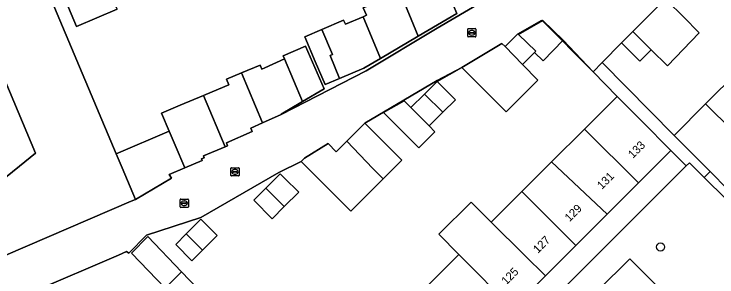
# Model space of a CAD drawing. Extents: x 159960 to 160866, y 382700 to 383354.
# Drawn here: x 160180.5 to 160265.7, y 383247.3 to 383279.2 of the extents above; entities that cross this region are included whole.
import ezdxf

# ---------------------------------------------------------------- set-up
doc = ezdxf.new("R2010")
doc.units = 0
for name, color, linetype in [('IMGEO_Boom', 7, 'Continuous'), ('IMGEO_Erf', 7, 'Continuous'), ('IMGEO_Hek', 7, 'Continuous'), ('IMGEO_Kolk', 7, 'Continuous'), ('IMGEO_Muur', 7, 'Continuous'), ('IMGEO_Pand', 7, 'Continuous'), ('IMGEO_Pand_nummerreeks', 7, 'Continuous'), ('IMGEO_Parkeervlak_open', 7, 'Continuous'), ('IMGEO_Rijbaan_lokaal_open', 7, 'Continuous'), ('IMGEO_Rioolput', 7, 'Continuous'), ('IMGEO_Voetpad_open', 7, 'Continuous')]:
    doc.layers.add(name, color=color, linetype=linetype)

msp = doc.modelspace()

# ---------------------------------------------------------------- linework, layer by layer
at = {"layer": 'IMGEO_Boom'}
msp.add_circle((160258.856, 383250.978), 0.489, dxfattribs=at)
at = {"layer": 'IMGEO_Erf'}
for points in [[(160266.216, 383293.194), (160261.754, 383290.535), (160263.274, 383287.861), (160261.51, 383286.857), (160261.743, 383286.447), (160262.389, 383285.314), (160264.398, 383283.518), (160259.67, 383280.828), (160261.621, 383278.874), (160263.551, 383276.941), (160259.686, 383272.913), (160257.707, 383274.874), (160256.335, 383273.504), (160254.138, 383275.705), (160251.785, 383273.342), (160260.491, 383264.497), (160264.32, 383268.32), (160268.247, 383272.242)], [(160183.004, 383285.712), (160192.859, 383262.277), (160199.282, 383265.002), (160198.369, 383267.186), (160200.633, 383268.147), (160203.442, 383269.339), (160203.718, 383269.456), (160206.503, 383270.638), (160206.224, 383271.296), (160208.052, 383272.072), (160210.311, 383273.03), (160210.519, 383272.54), (160210.88, 383272.7), (160213.279, 383273.761), (160213.118, 383274.125), (160215.792, 383275.307), (160218.073, 383270.149), (160215.452, 383268.606), (160213.76, 383267.611), (160213.267, 383267.321), (160212.842, 383267.071), (160212.865, 383267.016), (160223.145, 383272.34), (160231.792, 383277.479), (160248.64, 383287.39)], [(160192.97, 383279.801), (160188.056, 383277.715), (160186.423, 383281.562)], [(160230.525, 383246.193), (160234.338, 383250), (160234.412, 383250.073), (160231.985, 383252.518), (160235.896, 383256.424), (160238.338, 383253.994), (160242.052, 383257.703), (160245.647, 383261.293), (160249.618, 383265.258), (160253.591, 383269.225), (160250.674, 383272.217), (160247.039, 383276.034), (160244.609, 383273.533), (160243.565, 383274.546), (160242.115, 383273.097), (160243.971, 383271.194), (160240.133, 383267.363), (160234.771, 383272.735), (160231.773, 383271.153), (160223.016, 383266.001), (160227.495, 383261.515), (160225.213, 383259.237), (160221.301, 383255.332), (160220.102, 383256.532), (160215.296, 383261.343), (160212.589, 383260.015), (160203.125, 383254.533), (160196.55, 383252.407), (160194.374, 383250.234), (160194.125, 383250.434), (160193.118, 383250), (160182.733, 383245.525)], [(160208.233, 383207.203), (160251.131, 383250), (160261.979, 383260.823), (160260.119, 383262.687), (160256.164, 383258.737), (160252.364, 383254.944), (160248.59, 383251.176), (160247.413, 383250), (160244.887, 383247.478), (160240.918, 383243.515)], [(160267.032, 383257.946), (160264.852, 383260.129), (160264.14, 383259.417), (160269.505, 383254.094)]]:
    msp.add_lwpolyline(points, dxfattribs=at)
for points in [[(160231.939, 383284.582), (160234.143, 383279.263), (160229.485, 383276.528), (160224.882, 383273.826), (160222.897, 383272.661), (160219.927, 383271.4), (160218.177, 383270.657), (160216.997, 383273.438), (160215.712, 383276.465), (160217.781, 383277.343), (160220.432, 383278.468), (160220.641, 383277.976), (160222.782, 383278.884), (160223.197, 383279.06), (160222.807, 383279.979), (160227.268, 383281.872), (160227.355, 383281.909), (160227.093, 383282.525)], [(160229.56, 383263.005), (160225.282, 383267.288), (160227.765, 383268.699), (160228.302, 383268.161), (160228.599, 383267.864), (160230.237, 383269.5), (160231.791, 383271.051), (160233.98, 383268.829), (160232.444, 383267.296), (160230.803, 383265.657), (160231.508, 383264.951)], [(160211.774, 383254.407), (160209.542, 383256.642), (160211.003, 383258.1), (160212.757, 383259.851), (160213.279, 383259.328), (160214.989, 383257.616), (160213.236, 383255.866)], [(160202.046, 383249.296), (160200.068, 383251.276), (160201.356, 383252.562), (160203.129, 383254.333), (160205.107, 383252.351), (160203.328, 383250.576)], [(160200.785, 383247.974), (160204.653, 383243.924), (160202.66, 383241.936), (160198.783, 383245.978), (160194.708, 383250.244), (160196.709, 383252.241)]]:
    msp.add_lwpolyline(points, close=True, dxfattribs=at)
at = {"layer": 'IMGEO_Hek'}
msp.add_lwpolyline([(160251.785, 383273.342), (160254.138, 383275.705)], dxfattribs=at)
at = {"layer": 'IMGEO_Kolk'}
for p, q in [((160235.471, 383276.517), (160235.471, 383277.369)), ((160235.546, 383277.443), (160236.398, 383277.443)), ((160235.73, 383276.937), (160235.73, 383276.949)), ((160236.168, 383276.9), (160235.77, 383276.9)), ((160235.773, 383276.986), (160236.171, 383276.986)), ((160235.959, 383277.223), (160235.984, 383277.223)), ((160236.214, 383276.949), (160236.214, 383276.937)), ((160236.472, 383277.369), (160236.472, 383276.517)), ((160236.398, 383276.443), (160235.546, 383276.443)), ((160235.982, 383276.663), (160235.957, 383276.663)), ((160206.837, 383260.585), (160207.689, 383260.585)), ((160206.762, 383259.659), (160206.762, 383260.511)), ((160207.021, 383260.079), (160207.021, 383260.091)), ((160207.459, 383260.042), (160207.061, 383260.042)), ((160207.064, 383260.128), (160207.462, 383260.128)), ((160207.273, 383259.805), (160207.248, 383259.805)), ((160207.25, 383260.365), (160207.275, 383260.365)), ((160207.505, 383260.091), (160207.505, 383260.079)), ((160207.763, 383260.511), (160207.763, 383259.659)), ((160207.689, 383259.585), (160206.837, 383259.585))]:
    msp.add_line(p, q, dxfattribs=at)
for points in [[(160235.471, 383276.517), (160235.471, 383277.369)], [(160235.546, 383277.443), (160236.398, 383277.443)], [(160236.472, 383277.369), (160236.472, 383276.517)], [(160236.398, 383276.443), (160235.546, 383276.443)], [(160206.837, 383260.585), (160207.689, 383260.585)], [(160206.762, 383259.659), (160206.762, 383260.511)], [(160207.763, 383260.511), (160207.763, 383259.659)], [(160207.689, 383259.585), (160206.837, 383259.585)]]:
    msp.add_lwpolyline(points, dxfattribs=at)
for centre, radius, start, end in [((160235.548, 383277.367), 0.0765, 91.55205, 178.44795), ((160235.548, 383277.367), 0.0765, 91.55205, 178.44795), ((160235.77, 383276.946), 0.0403, 85.87752, 175.75265), ((160235.767, 383276.936), 0.0366, 178.93798, 274.71019), ((160236.171, 383276.943), 0.043, 264.86636, 352.45326), ((160236.175, 383276.948), 0.0386, 1.73085, 96.63898), ((160236.396, 383277.367), 0.0765, 1.55205, 88.44795), ((160236.396, 383277.367), 0.0765, 1.55205, 88.44795), ((160235.548, 383276.519), 0.0765, 181.55205, 268.44795), ((160235.548, 383276.519), 0.0765, 181.55205, 268.44795), ((160236.396, 383276.519), 0.0765, 271.55205, 358.44795), ((160236.396, 383276.519), 0.0765, 271.55205, 358.44795), ((160206.839, 383260.509), 0.0765, 91.55205, 178.44795), ((160206.839, 383260.509), 0.0765, 91.55205, 178.44795), ((160207.687, 383260.509), 0.0765, 1.55205, 88.44795), ((160207.687, 383260.509), 0.0765, 1.55205, 88.44795), ((160207.061, 383260.088), 0.0403, 85.87752, 175.75265), ((160207.058, 383260.078), 0.0366, 178.93798, 274.71019), ((160207.462, 383260.085), 0.043, 264.86636, 352.45326), ((160207.466, 383260.09), 0.0386, 1.73085, 96.63898), ((160206.839, 383259.661), 0.0765, 181.55205, 268.44795), ((160206.839, 383259.661), 0.0765, 181.55205, 268.44795), ((160207.687, 383259.661), 0.0765, 271.55205, 358.44795), ((160207.687, 383259.661), 0.0765, 271.55205, 358.44795)]:
    msp.add_arc(centre, radius, start, end, dxfattribs=at)
for centre, major_axis, ratio, start_param, end_param in [((160235.958, 383276.943), (-0.387, 0.002), 0.722429, 4.712389, 7.853982), ((160235.983, 383276.943), (-0.39, 0.002), 0.717154, 1.570796, 4.712389), ((160207.249, 383260.085), (-0.387, 0.002), 0.722429, 4.712389, 7.853982), ((160207.274, 383260.085), (-0.39, 0.002), 0.717154, 1.570796, 4.712389)]:
    msp.add_ellipse(centre, major_axis=major_axis, ratio=ratio, start_param=start_param, end_param=end_param, dxfattribs=at)
at = {"layer": 'IMGEO_Muur'}
for points in [[(160241.543, 383276.818), (160244.454, 383278.474), (160250.674, 383272.217)], [(160231.791, 383271.051), (160234.771, 383272.735)]]:
    msp.add_lwpolyline(points, dxfattribs=at)
at = {"layer": 'IMGEO_Pand'}
for points in [[(160183.004, 383285.712), (160181.841, 383288.432), (160181.644, 383288.894), (160181.208, 383288.685), (160173.362, 383285.397), (160183.09, 383262.358), (160173.574, 383254.679), (160178.179, 383250), (160178.563, 383249.609), (160179.477, 383250), (160194.681, 383256.511), (160195.189, 383256.729), (160193.573, 383260.577), (160192.859, 383262.277)], [(160189.337, 383288.318), (160185.578, 383286.722), (160184.438, 383286.238), (160186.423, 383281.562), (160188.056, 383277.715), (160192.97, 383279.801)], [(160183.09, 383262.358), (160173.362, 383285.397), (160163.306, 383284.974), (160163.378, 383283.205), (160163.482, 383280.605), (160164.075, 383268.216), (160167.723, 383268.339), (160167.679, 383269.669), (160168.759, 383269.706), (160168.726, 383270.685), (160172.805, 383270.823), (160175.164, 383270.903), (160178.228, 383263.099), (160164.266, 383262.534), (160164.765, 383250), (160164.849, 383247.905), (160167.549, 383250), (160173.574, 383254.679)], [(160234.143, 383279.263), (160231.939, 383284.582), (160227.093, 383282.525), (160227.355, 383281.909), (160227.268, 383281.872), (160229.485, 383276.528)], [(160224.882, 383273.826), (160229.485, 383276.528), (160227.268, 383281.872), (160222.807, 383279.979), (160223.197, 383279.06), (160222.782, 383278.884)], [(160259.67, 383280.828), (160259.498, 383281.119), (160255.486, 383277.074), (160257.707, 383274.874), (160259.686, 383272.913), (160263.551, 383276.941), (160261.621, 383278.874)], [(160224.882, 383273.826), (160222.782, 383278.884), (160220.641, 383277.976), (160220.432, 383278.468), (160217.781, 383277.343), (160219.066, 383274.317), (160218.785, 383274.198), (160219.927, 383271.4), (160222.897, 383272.661)], [(160241.652, 383276.713), (160243.737, 383274.715), (160243.565, 383274.546), (160244.609, 383273.533), (160247.039, 383276.034), (160244.585, 383278.418)], [(160218.785, 383274.198), (160219.066, 383274.317), (160217.781, 383277.343), (160215.712, 383276.465), (160216.997, 383273.438), (160218.177, 383270.657), (160219.927, 383271.4)], [(160241.652, 383276.713), (160241.543, 383276.818), (160239.998, 383275.267), (160242.115, 383273.097), (160243.565, 383274.546), (160243.737, 383274.715)], [(160255.486, 383277.074), (160254.138, 383275.705), (160256.335, 383273.504), (160257.707, 383274.874)], [(160215.452, 383268.606), (160218.073, 383270.149), (160215.792, 383275.307), (160213.118, 383274.125), (160213.279, 383273.761)], [(160242.115, 383273.097), (160239.998, 383275.267), (160239.609, 383275.636), (160234.771, 383272.735), (160240.133, 383267.363), (160243.971, 383271.194)], [(160213.279, 383273.761), (160210.88, 383272.7), (160210.519, 383272.54), (160210.311, 383273.03), (160208.052, 383272.072), (160210.605, 383266.014), (160212.865, 383267.016), (160212.842, 383267.071), (160213.267, 383267.321), (160213.76, 383267.611), (160215.452, 383268.606)], [(160208.052, 383272.072), (160206.224, 383271.296), (160206.503, 383270.638), (160203.718, 383269.456), (160203.442, 383269.339), (160206.057, 383263.124), (160206.37, 383263.255), (160206.241, 383263.589), (160209.326, 383264.979), (160209.161, 383265.373), (160210.605, 383266.014)], [(160274.821, 383265.724), (160268.247, 383272.242), (160264.32, 383268.32), (160270.895, 383261.804)], [(160232.444, 383267.296), (160233.98, 383268.829), (160231.791, 383271.051), (160230.237, 383269.5)], [(160199.282, 383265.002), (160200.005, 383263.307), (160201.168, 383260.566), (160203.299, 383261.469), (160203.216, 383261.652), (160203.536, 383261.793), (160203.429, 383262.024), (160206.057, 383263.124), (160203.442, 383269.339), (160200.633, 383268.147), (160198.369, 383267.186)], [(160232.444, 383267.296), (160230.237, 383269.5), (160228.599, 383267.864), (160230.803, 383265.657)], [(160249.618, 383265.258), (160256.164, 383258.737), (160260.119, 383262.687), (160256.586, 383266.225), (160253.591, 383269.225)], [(160228.599, 383267.864), (160228.302, 383268.161), (160227.765, 383268.699), (160225.282, 383267.288), (160229.56, 383263.005), (160231.508, 383264.951), (160230.803, 383265.657)], [(160264.32, 383268.32), (160260.491, 383264.497), (160264.852, 383260.129), (160267.032, 383257.946), (160270.895, 383261.804)], [(160220.807, 383263.786), (160223.977, 383260.476), (160225.213, 383259.237), (160227.495, 383261.515), (160223.016, 383266.001)], [(160199.282, 383265.002), (160192.859, 383262.277), (160193.573, 383260.577), (160195.189, 383256.729), (160199.573, 383259.303), (160199.273, 383259.763), (160201.168, 383260.566), (160200.005, 383263.307)], [(160249.618, 383265.258), (160245.647, 383261.293), (160252.364, 383254.944), (160256.164, 383258.737)], [(160220.807, 383263.786), (160219.525, 383262.501), (160218.554, 383263.505), (160215.697, 383261.743), (160215.296, 383261.343), (160220.102, 383256.532), (160221.301, 383255.332), (160225.213, 383259.237), (160223.977, 383260.476)], [(160242.052, 383257.703), (160248.59, 383251.176), (160252.364, 383254.944), (160245.647, 383261.293)], [(160213.236, 383255.866), (160214.989, 383257.616), (160213.279, 383259.328), (160212.757, 383259.851), (160211.003, 383258.1)], [(160213.236, 383255.866), (160211.003, 383258.1), (160209.542, 383256.642), (160211.774, 383254.407)], [(160242.052, 383257.703), (160238.338, 383253.994), (160242.352, 383250), (160244.887, 383247.478), (160247.413, 383250), (160248.59, 383251.176)], [(160242.352, 383250), (160238.338, 383253.994), (160235.896, 383256.424), (160231.985, 383252.518), (160234.412, 383250.073), (160234.484, 383250), (160240.918, 383243.515), (160244.887, 383247.478)], [(160203.129, 383254.333), (160201.356, 383252.562), (160203.328, 383250.576), (160205.107, 383252.351)], [(160198.783, 383245.978), (160200.785, 383247.974), (160196.709, 383252.241), (160194.708, 383250.244)], [(160201.356, 383252.562), (160200.068, 383251.276), (160202.046, 383249.296), (160203.328, 383250.576)], [(160236.994, 383239.598), (160240.918, 383243.515), (160234.484, 383250), (160234.412, 383250.073), (160234.338, 383250), (160230.525, 383246.193)], [(160200.785, 383247.974), (160198.783, 383245.978), (160202.66, 383241.936), (160204.653, 383243.924)]]:
    msp.add_lwpolyline(points, close=True, dxfattribs=at)
at = {"layer": 'IMGEO_Parkeervlak_open'}
msp.add_lwpolyline([(160262.591, 383242.059), (160255.124, 383249.551), (160251.269, 383245.72), (160273.314, 383223.64), (160277.168, 383227.432)], close=True, dxfattribs=at)
at = {"layer": 'IMGEO_Rijbaan_lokaal_open'}
for points in [[(160248.64, 383287.39), (160231.792, 383277.479), (160223.145, 383272.34), (160212.865, 383267.016), (160210.605, 383266.014), (160209.161, 383265.373), (160209.326, 383264.979), (160206.241, 383263.589), (160206.37, 383263.255), (160206.057, 383263.124), (160203.429, 383262.024), (160203.536, 383261.793), (160203.216, 383261.652), (160203.299, 383261.469), (160201.168, 383260.566), (160199.273, 383259.763), (160199.573, 383259.303), (160195.189, 383256.729), (160194.681, 383256.511), (160179.477, 383250)], [(160234.771, 383272.735), (160239.609, 383275.636), (160239.998, 383275.267), (160241.543, 383276.818), (160241.652, 383276.713), (160244.585, 383278.418), (160247.039, 383276.034), (160250.674, 383272.217), (160251.785, 383273.342), (160254.138, 383275.705), (160255.486, 383277.074), (160259.498, 383281.119)], [(160174.314, 383238.292), (160182.172, 383246.116), (160182.733, 383245.525), (160193.118, 383250), (160194.125, 383250.434), (160194.374, 383250.234), (160196.55, 383252.407), (160203.125, 383254.533), (160212.589, 383260.015), (160215.296, 383261.343), (160215.697, 383261.743), (160218.554, 383263.505), (160219.525, 383262.501), (160220.807, 383263.786), (160223.016, 383266.001), (160231.773, 383271.153), (160234.771, 383272.735)]]:
    msp.add_lwpolyline(points, dxfattribs=at)
at = {"layer": 'IMGEO_Rioolput'}
for p, q in [((160200.61, 383255.853), (160200.61, 383256.705)), ((160200.685, 383256.779), (160201.537, 383256.779)), ((160200.869, 383256.273), (160200.869, 383256.285)), ((160200.912, 383256.322), (160201.31, 383256.322)), ((160201.098, 383256.559), (160201.123, 383256.559)), ((160201.353, 383256.285), (160201.353, 383256.273)), ((160201.611, 383256.705), (160201.611, 383255.853)), ((160201.537, 383255.779), (160200.685, 383255.779)), ((160201.307, 383256.236), (160200.909, 383256.236)), ((160201.121, 383255.999), (160201.096, 383255.999))]:
    msp.add_line(p, q, dxfattribs=at)
for points in [[(160200.61, 383255.853), (160200.61, 383256.705)], [(160200.685, 383256.779), (160201.537, 383256.779)], [(160201.611, 383256.705), (160201.611, 383255.853)], [(160201.537, 383255.779), (160200.685, 383255.779)]]:
    msp.add_lwpolyline(points, dxfattribs=at)
for centre, radius, start, end in [((160200.687, 383256.703), 0.0765, 91.55205, 178.44795), ((160200.687, 383256.703), 0.0765, 91.55205, 178.44795), ((160200.909, 383256.282), 0.0403, 85.87752, 175.75265), ((160200.906, 383256.272), 0.0366, 178.93798, 274.71019), ((160201.31, 383256.279), 0.043, 264.86636, 352.45326), ((160201.314, 383256.284), 0.0386, 1.73085, 96.63898), ((160201.535, 383256.703), 0.0765, 1.55205, 88.44795), ((160201.535, 383256.703), 0.0765, 1.55205, 88.44795), ((160200.687, 383255.855), 0.0765, 181.55205, 268.44795), ((160200.687, 383255.855), 0.0765, 181.55205, 268.44795), ((160201.535, 383255.855), 0.0765, 271.55205, 358.44795), ((160201.535, 383255.855), 0.0765, 271.55205, 358.44795)]:
    msp.add_arc(centre, radius, start, end, dxfattribs=at)
for centre, major_axis, ratio, start_param, end_param in [((160201.097, 383256.279), (-0.387, 0.002), 0.722429, 4.712389, 7.853982), ((160201.122, 383256.279), (-0.39, 0.002), 0.717154, 1.570796, 4.712389)]:
    msp.add_ellipse(centre, major_axis=major_axis, ratio=ratio, start_param=start_param, end_param=end_param, dxfattribs=at)
at = {"layer": 'IMGEO_Voetpad_open'}
msp.add_lwpolyline([(160251.785, 383273.342), (160250.674, 383272.217), (160253.591, 383269.225), (160256.586, 383266.225), (160260.119, 383262.687), (160261.979, 383260.823), (160262.35, 383261.193), (160264.14, 383259.417), (160264.852, 383260.129), (160260.491, 383264.497)], close=True, dxfattribs=at)
msp.add_lwpolyline([(160269.505, 383254.094), (160264.14, 383259.417), (160262.35, 383261.193), (160261.979, 383260.823), (160251.131, 383250), (160208.233, 383207.203), (160206.442, 383208.991), (160204.129, 383206.68), (160208.066, 383202.745), (160242.997, 383237.496), (160250.989, 383245.448), (160251.269, 383245.72), (160255.124, 383249.551), (160262.591, 383242.059), (160263.358, 383242.823), (160270.515, 383250)], dxfattribs=at)

# ---------------------------------------------------------------- texts
at = {"layer": 'IMGEO_Pand_nummerreeks'}
for s, rotation, p in [('133', 44.9552, (160255.507, 383261.643)), ('131', 44.9552, (160251.749, 383257.891)), ('129', 44.9552, (160247.828, 383253.976)), ('127', 44.9552, (160243.988, 383250.143)), ('125', 44.95427, (160240.15, 383246.309))]:
    msp.add_text(s, height=1, rotation=rotation, dxfattribs=at).set_placement(p)

doc.saveas('drawing.dxf')
